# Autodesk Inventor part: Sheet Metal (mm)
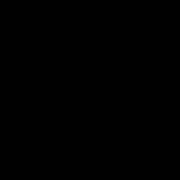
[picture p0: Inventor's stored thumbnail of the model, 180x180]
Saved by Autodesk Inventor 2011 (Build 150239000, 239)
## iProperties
Shininess: 64.0
Length Units: 11269
Angle Units: 11279
Time Units: 11290
Mass Units: 11283
Length Display Precision: 3
Angle Display Precision: 2
Compacted: True
Part Number: Sheet Metal (mm)
Document SubType Name: Sheet Metal
Created: 2002-07
Density: 1 g/cm^3
Sheet Metal Rule: Default
Density: 0.0
Volumn: 0.0
Area: 0.0
PropertySet Name: Model Information
Control State: 0
Master: False
Checked Out: False
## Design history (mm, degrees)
other parameters: "Thickness" = 0.5, "BendRadius" = 0.5 (= Thickness), "BendReliefWidth" = 0.5 (= Thickness), "BendReliefDepth" = 0.25 (= 0.5 x Thickness), "CornerReliefSize" = 2 (= 4 x Thickness), "SeamGap" = 0.01, "MinimumRemnant" = 1 (= 2 x Thickness), "TransitionRadius" = 0.5 (= BendRadius), "JacobiRadiusSize" = 0.5 (= BendRadius), "GapSize" = 0.5 (= Thickness)
